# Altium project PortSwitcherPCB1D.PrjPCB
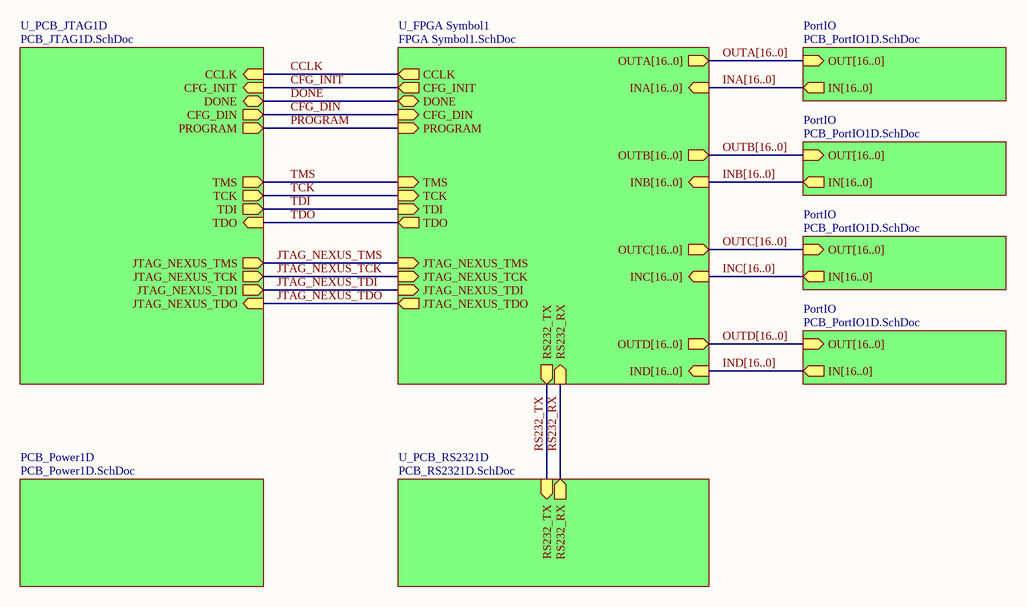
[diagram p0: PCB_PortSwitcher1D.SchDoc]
7 sheets, 152 parts. Net scope: hierarchical (ports join the sheet entries above them; power ports are global).
Board file: PortSwitcher1D.PCBDOC
Sheets:
  PCB_PortSwitcher1D.SchDoc
    PCB_Power1D = PCB_Power1D.SchDoc
    U_PCB_JTAG1D = PCB_JTAG1D.SchDoc
    PortIO = PCB_PortIO1D.SchDoc
    PortIO = PCB_PortIO1D.SchDoc
    PortIO = PCB_PortIO1D.SchDoc
    PortIO = PCB_PortIO1D.SchDoc
    U_FPGA Symbol1 = FPGA Symbol1.SchDoc
      U_FPGA Sheet1 = FPGA Sheet1.SchDoc
    U_PCB_RS2321D = PCB_RS2321D.SchDoc

## Sheet PCB_PortSwitcher1D.SchDoc
size A4; Organization: Altium Limited; Address1: L3, 12a Rodborough Rd; Address2: Frenchs Forest; Address3: NSW; Address4: Australia 2086; DocumentNumber: 1; SheetNumber: 1; SheetTotal: 7

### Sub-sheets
PCB_Power1D = PCB_Power1D.SchDoc: no entries
PortIO = PCB_PortIO1D.SchDoc: OUT[16..0] (in), IN[16..0] (out)
PortIO = PCB_PortIO1D.SchDoc: OUT[16..0] (in), IN[16..0] (out)
PortIO = PCB_PortIO1D.SchDoc: OUT[16..0] (in), IN[16..0] (out)
PortIO = PCB_PortIO1D.SchDoc: OUT[16..0] (in), IN[16..0] (out)
U_FPGA Symbol1 = FPGA Symbol1.SchDoc: CFG_INIT (out), CFG_DIN (in), PROGRAM (in), DONE (bidir), CCLK (out), TMS (in), TCK (in), TDI (in), JTAG_NEXUS_TMS (in), JTAG_NEXUS_TCK (in), JTAG_NEXUS_TDI (in), JTAG_NEXUS_TDO (out), TDO (out), OUTD[16..0] (out), OUTC[16..0] (out), OUTB[16..0] (out), OUTA[16..0] (out), IND[16..0] (in), INC[16..0] (in), INB[16..0] (in), INA[16..0] (in), RS232_TX (out), RS232_RX (in)
U_PCB_JTAG1D = PCB_JTAG1D.SchDoc: TDO (in), TDI (out), TCK (out), TMS (out), DONE (bidir), PROGRAM (out), CCLK (in), JTAG_NEXUS_TMS (out), JTAG_NEXUS_TCK (out), JTAG_NEXUS_TDI (out), JTAG_NEXUS_TDO (in), CFG_DIN (out), CFG_INIT (in)
U_PCB_RS2321D = PCB_RS2321D.SchDoc: RS232_RX (out), RS232_TX (in)

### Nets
CCLK: sheet U_PCB_JTAG1D/CCLK, sheet U_FPGA Symbol1/CCLK
CFG_DIN: sheet U_PCB_JTAG1D/CFG_DIN, sheet U_FPGA Symbol1/CFG_DIN
CFG_INIT: sheet U_PCB_JTAG1D/CFG_INIT, sheet U_FPGA Symbol1/CFG_INIT
DONE: sheet U_PCB_JTAG1D/DONE, sheet U_FPGA Symbol1/DONE
JTAG_NEXUS_TCK: sheet U_PCB_JTAG1D/JTAG_NEXUS_TCK, sheet U_FPGA Symbol1/JTAG_NEXUS_TCK
JTAG_NEXUS_TDI: sheet U_PCB_JTAG1D/JTAG_NEXUS_TDI, sheet U_FPGA Symbol1/JTAG_NEXUS_TDI
JTAG_NEXUS_TDO: sheet U_PCB_JTAG1D/JTAG_NEXUS_TDO, sheet U_FPGA Symbol1/JTAG_NEXUS_TDO
JTAG_NEXUS_TMS: sheet U_PCB_JTAG1D/JTAG_NEXUS_TMS, sheet U_FPGA Symbol1/JTAG_NEXUS_TMS
PROGRAM: sheet U_PCB_JTAG1D/PROGRAM, sheet U_FPGA Symbol1/PROGRAM
RS232_RX: sheet U_FPGA Symbol1/RS232_RX, sheet U_PCB_RS2321D/RS232_RX
RS232_TX: sheet U_FPGA Symbol1/RS232_TX, sheet U_PCB_RS2321D/RS232_TX
TCK: sheet U_PCB_JTAG1D/TCK, sheet U_FPGA Symbol1/TCK
TDI: sheet U_PCB_JTAG1D/TDI, sheet U_FPGA Symbol1/TDI
TDO: sheet U_PCB_JTAG1D/TDO, sheet U_FPGA Symbol1/TDO
TMS: sheet U_PCB_JTAG1D/TMS, sheet U_FPGA Symbol1/TMS

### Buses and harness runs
bus INA[16..0] = sheet PortIO/IN[16..0] = sheet U_FPGA Symbol1/INA[16..0]
bus INB[16..0] = sheet PortIO/IN[16..0] = sheet U_FPGA Symbol1/INB[16..0]
bus INC[16..0] = sheet PortIO/IN[16..0] = sheet U_FPGA Symbol1/INC[16..0]
bus IND[16..0] = sheet PortIO/IN[16..0] = sheet U_FPGA Symbol1/IND[16..0]
bus OUTA[16..0] = sheet PortIO/OUT[16..0] = sheet U_FPGA Symbol1/OUTA[16..0]
bus OUTB[16..0] = sheet PortIO/OUT[16..0] = sheet U_FPGA Symbol1/OUTB[16..0]
bus OUTC[16..0] = sheet PortIO/OUT[16..0] = sheet U_FPGA Symbol1/OUTC[16..0]
bus OUTD[16..0] = sheet PortIO/OUT[16..0] = sheet U_FPGA Symbol1/OUTD[16..0]

## Sheet PCB_Power1D.SchDoc
size A4; Organization: Altium Limited; Address1: L3, 12a Rodborough Rd; Address2: Frenchs Forest; Address3: NSW; Address4: Australia 2086; DocumentNumber: 2; SheetNumber: 2; SheetTotal: 7
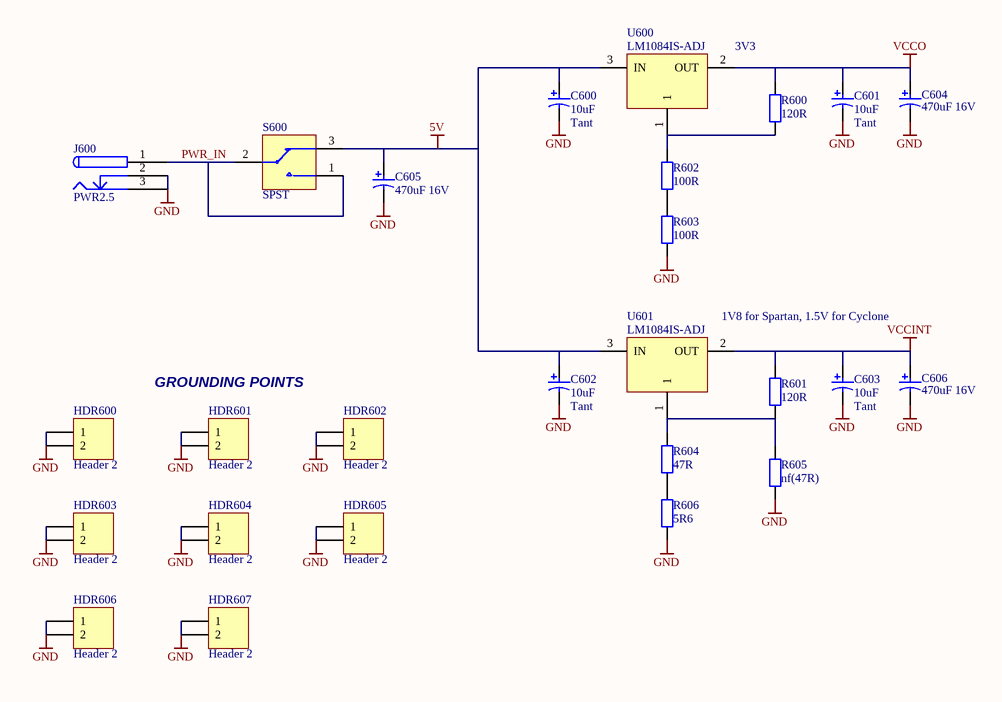
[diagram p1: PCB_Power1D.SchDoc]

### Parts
C600  10uF  Capacitor Type: Tant  [MCCT-B]
C601  10uF  Capacitor Type: Tant  [MCCT-B]
C602  10uF  Capacitor Type: Tant  [MCCT-B]
C603  10uF  Capacitor Type: Tant  [MCCT-B]
C604  470uF 16V  [RB8/3.5]
C605  470uF 16V  [RB8/3.5]
C606  470uF 16V  [RB8/3.5]
HDR600  Header 2  [HDR1X2]
HDR601  Header 2  [HDR1X2]
HDR602  Header 2  [HDR1X2]
HDR603  Header 2  [HDR1X2]
HDR604  Header 2  [HDR1X2]
HDR605  Header 2  [HDR1X2]
HDR606  Header 2  [HDR1X2]
HDR607  Header 2  [HDR1X2]
J600  PWR2.5  [PWR2.5]
R600  120R  [CC2012-0805]
R601  120R  [CC2012-0805]
R602  100R  [CC2012-0805]
R603  100R  [CC2012-0805]
R604  47R  [CC2012-0805]
R605  nf(47R)  [CC2012-0805]
R606  5R6  [CC2012-0805]
S600  SPST  [PCB_SWITCH]
U600  LM1084IS-ADJ  [TO-263]
U601  LM1084IS-ADJ  [TO-263]

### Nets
5V: C600.1 C602.1 C605.1 S600.3 U600.3(IN) U601.3(IN)
GND: C600.2 C601.2 C602.2 C603.2 C604.2 C605.2 C606.2 HDR600.1 HDR600.2 HDR601.1 HDR601.2 HDR602.1 HDR602.2 HDR603.1 HDR603.2 HDR604.1 HDR604.2 HDR605.1 HDR605.2 HDR606.1 HDR606.2 HDR607.1 HDR607.2 J600.2 J600.3 R603.1 R605.1 R606.1
VCCINT: C603.1 C606.1 R601.2 U601.2(OUT)
VCCO: C601.1 C604.1 R600.2 U600.2(OUT)
PWR_IN: J600.1 S600.1 S600.2
NetR600_1: R600.1 R602.2 U600.1
NetR601_1: R601.1 R604.2 R605.2 U601.1
NetR602_1: R602.1 R603.2
NetR604_1: R604.1 R606.2

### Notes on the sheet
- 3V3
- (near U601) 1V8 for Spartan, 1.5V for Cyclone
- (near HDR601) GROUNDING POINTS

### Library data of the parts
C600-C606 = CAP_POLAR: Polar Capacitor; Fitted: True
HDR600-HDR607 = Header 2: Header, 2-Pin; Manufacturer: Generic Components; Class I: Connector; Fitted: True
J600 = PWR2.5: Low Voltage Power Supply Sonnector; Fitted: True
R600-R604 R606 = Res2: Resistor; Manufacturer: Generic Components; Class I: Passive
R605 = Res2: Resistor; Manufacturer: Generic Components; Class I: Passive; Fitted: False
S600 = PCB_MOUNT_SWITCH: SPDT Subminiature Toggle Switch; Fitted: True
U600 U601 = LM1084IS-ADJ: 5A Low Dropout Possitive Regulators; Fitted: True

## Sheet PCB_JTAG1D.SchDoc
size A4; Organization: Altium Limited; Address1: L3, 12a Rodborough Rd; Address2: Frenchs Forest; Address3: NSW; Address4: Australia 2086; DocumentNumber: 4; SheetNumber: 4; SheetTotal: 7
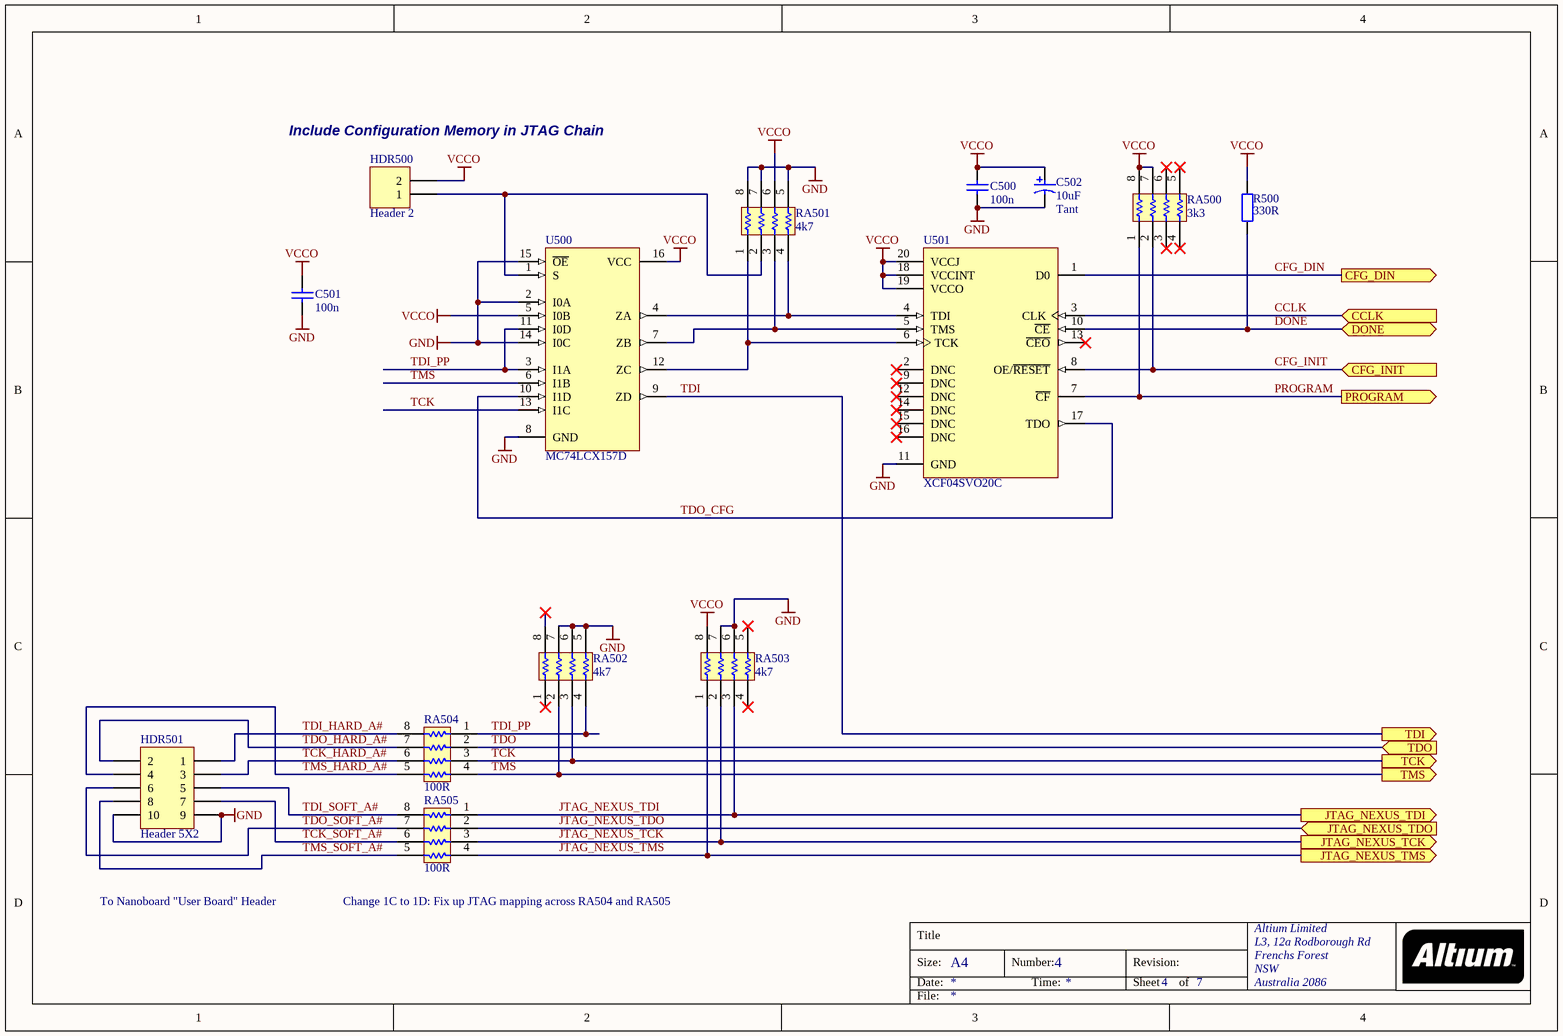
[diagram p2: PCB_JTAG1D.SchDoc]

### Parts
C500  100n  [CC2012-0805]
C501  100n  [CC2012-0805]
C502  10uF  Capacitor Type: Tant  [MCCT-B]
HDR500  Header 2  Usage: Include Configuration Memory in JTAG Chain  [HDR1X2]
HDR501  Header 5X2  Usage: To Nanoboard "User Board" Header  [HDR2X5]
R500  330R  [CC2012-0805]
RA500  3k3  [MNR34]
RA501  4k7  [MNR34]
RA502  4k7  [MNR34]
RA503  4k7  [MNR34]
RA504  100R  [MNR34]
RA505  100R  [MNR34]
U500  MC74LCX157D  [751B-05]
U501  XCF04SVO20C  [VO20]

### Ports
CCLK (in), CFG_DIN (out), CFG_INIT (in), DONE (bidir), JTAG_NEXUS_TCK (out), JTAG_NEXUS_TDI (out), JTAG_NEXUS_TDO (in), JTAG_NEXUS_TMS (out), PROGRAM (out), TCK (out), TDI (out), TDO (in), TMS (out)

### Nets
GND: C500.2 C501.2 C502.2 HDR501.9 HDR501.10 RA501.5 RA501.7 RA501.8 RA502.5 RA502.6 RA502.7 RA503.6 RA503.7 U500.2(I0A) U500.8(GND) U500.14(I0C) U500.15(~{OE}) U501.11(GND)
VCCO: C500.1 C501.1 C502.1 HDR500.2 R500.1 RA500.7 RA500.8 RA501.6 RA503.8 U500.5(I0B) U500.16(VCC) U501.18(VCCINT) U501.19(VCCO) U501.20(VCCJ)
CCLK: U501.3(CLK) ; port CCLK
CFG_DIN: U501.1(D0) ; port CFG_DIN
CFG_INIT: RA500.2 U501.8(OE/~{RESET}) ; port CFG_INIT
DONE: R500.2 U501.10(~{CE}) ; port DONE
JTAG_NEXUS_TCK: RA503.2 RA505.3 ; port JTAG_NEXUS_TCK
JTAG_NEXUS_TDI: RA503.3 RA505.1 ; port JTAG_NEXUS_TDI
JTAG_NEXUS_TDO: RA505.2 ; port JTAG_NEXUS_TDO
JTAG_NEXUS_TMS: RA503.1 RA505.4 ; port JTAG_NEXUS_TMS
PROGRAM: RA500.1 U501.7(~{CF}) ; port PROGRAM
TCK: RA502.3 RA504.3 U500.13(I1C) ; port TCK
TCK_HARD_A#: HDR501.3 RA504.6
TCK_SOFT_A#: HDR501.7 RA505.6
TDI: U500.9(ZD) ; port TDI
TDI_HARD_A#: HDR501.1 RA504.8
TDI_PP: RA502.4 RA504.1 U500.3(I1A) U500.11(I0D)
TDI_SOFT_A#: HDR501.5 RA505.8
TDO: RA504.2 ; port TDO
TDO_CFG: U500.10(I1D) U501.17(TDO)
TDO_HARD_A#: HDR501.2 RA504.7
TDO_SOFT_A#: HDR501.6 RA505.7
TMS: RA502.2 RA504.4 U500.6(I1B) ; port TMS
TMS_HARD_A#: HDR501.4 RA504.5
TMS_SOFT_A#: HDR501.8 RA505.5
NetHDR500_1: HDR500.1 RA501.2 U500.1(S)
NetRA501_1: RA501.1 U500.12(ZC) U501.6(TCK)
NetRA501_3: RA501.3 U500.7(ZB) U501.5(TMS)
NetRA501_4: RA501.4 U500.4(ZA) U501.4(TDI)

Not connected (* = marked no-connect by the designer): RA500 3* 4* 5* 6*; RA502 1* 8*; RA503 4* 5*; U501 2(DNC)* 9(DNC)* 12(DNC)* 13(~{CEO})* 14(DNC)* 15(DNC)* 16(DNC)*

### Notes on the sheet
- (near RA505) Change 1C to 1D: Fix up JTAG mapping across RA504 and RA505

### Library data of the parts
C500 C501 = CAP: Capacitor; Fitted: True
C502 = CAP_POLAR: Polar Capacitor; Fitted: True
HDR500 = Header 2: Header, 2-Pin; Manufacturer: Generic Components; Class I: Connector; Fitted: False
HDR501 = Header 5X2: Header, 5-Pin, Dual row; Manufacturer: Generic Components; Class I: Connector; Fitted: True
R500 = Res2: as R600 on sheet PCB_Power1D
RA500-RA505 = MNR34: 3216x4 Resistor Array; Fitted: True
U500 = MC74LCX157D: Low-Voltage Quad 2-Input Multiplexer with 5V-Tolerant Inputs (Non-Inverting); Manufacturer: ON Semiconductor; Package Information: Latest Revision: Oct-1999; Code - JEDEC: MS-012-AC; Code - IPC: SO16
U501 = XCF04SVO20C: XCF00S Series, Platform Flash In-System Programmable Configuration 3.3V PROM, 20-Pin TSOP, 4-Megabit, Commercial Grade; Manufacturer: Xilinx; Package Information: Latest Revision: ver1.0, May-2003; Code - JEDEC: MO-153-AC

## Sheet PCB_PortIO1D.SchDoc
size A4; Organization: Altium Limited; Address1: L3, 12a Rodborough Rd; Address2: Frenchs Forest; Address3: NSW; Address4: Australia 2086; DocumentNumber: 7; SheetNumber: 7; SheetTotal: 7
Used 4 times, as channels PortIO, PortIO, PortIO, PortIO. Parts and nets are listed once, with the designators drawn on the sheet.
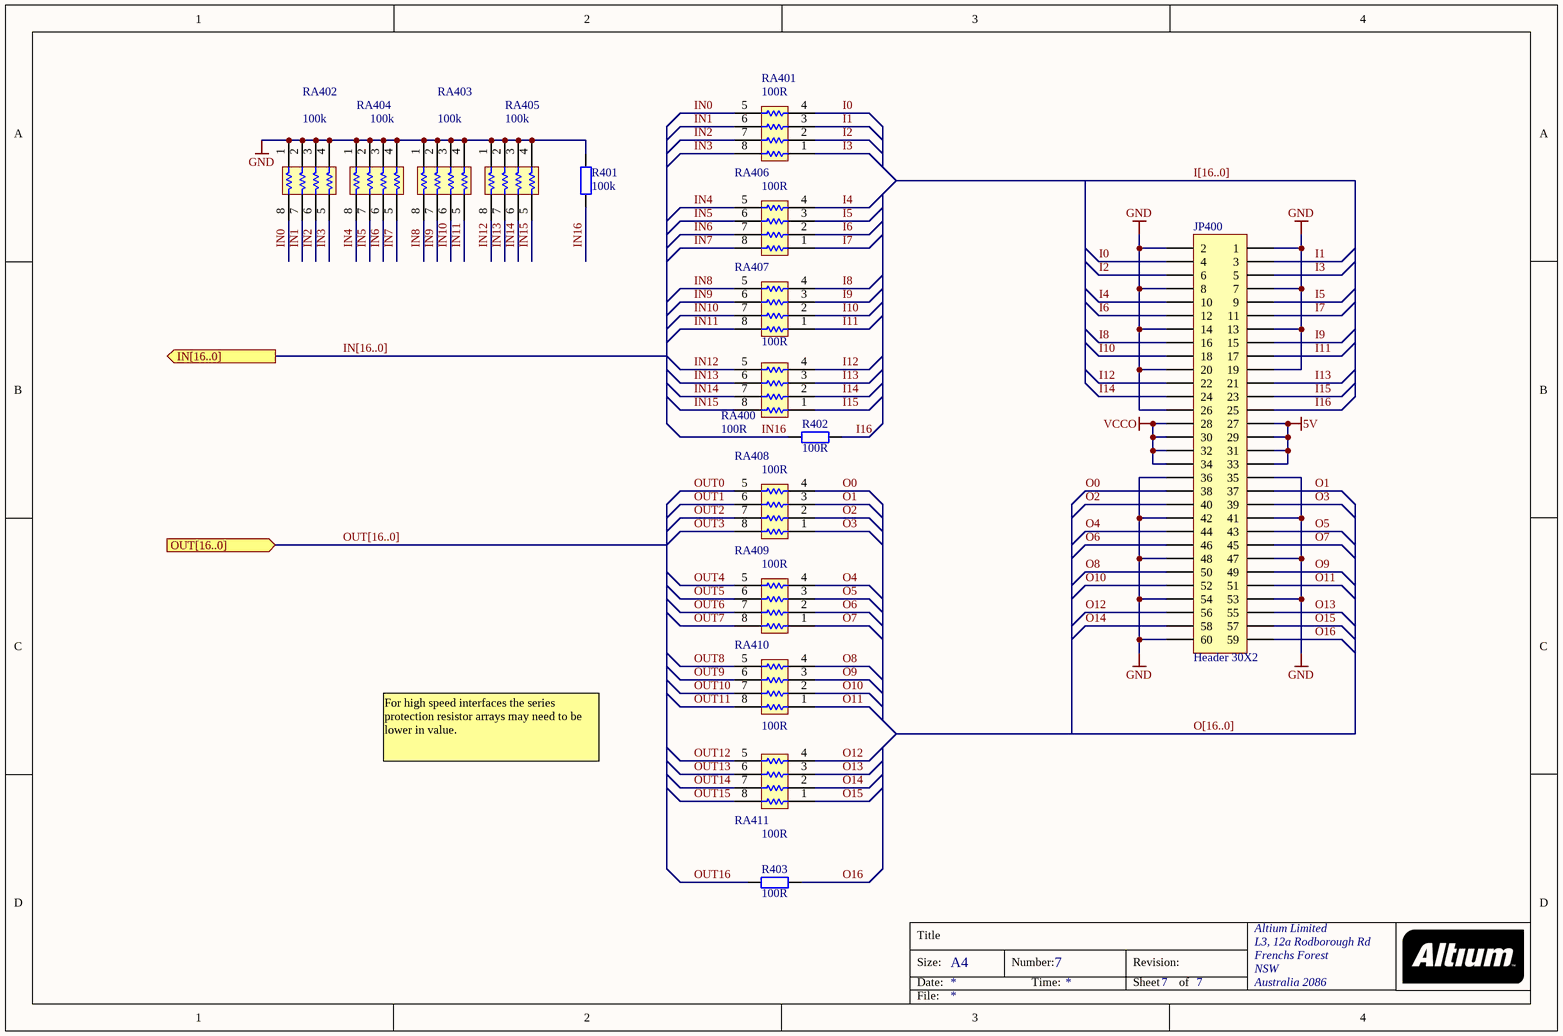
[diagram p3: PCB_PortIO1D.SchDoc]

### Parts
JP400  Header 30X2  [HDR2X30]
R401  100k  [CC2012-0805]
R402  100R  [CC2012-0805]
R403  100R  [CC2012-0805]
RA400  100R  [MNR34]
RA401  100R  [MNR34]
RA402  100k  [MNR34]
RA403  100k  [MNR34]
RA404  100k  [MNR34]
RA405  100k  [MNR34]
RA406  100R  [MNR34]
RA407  100R  [MNR34]
RA408  100R  [MNR34]
RA409  100R  [MNR34]
RA410  100R  [MNR34]
RA411  100R  [MNR34]

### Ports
IN[16..0] (out), OUT[16..0] (in)

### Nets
5V: JP400.27 JP400.29 JP400.31 JP400.33
GND: JP400.1 JP400.2 JP400.7 JP400.8 JP400.13 JP400.14 JP400.19 JP400.20 JP400.26 JP400.35 JP400.36 JP400.41 JP400.42 JP400.47 JP400.48 JP400.53 JP400.54 JP400.60 R401.1 RA402.1 RA402.2 RA402.3 RA402.4 RA403.1 RA403.2 RA403.3 RA403.4 RA404.1 RA404.2 RA404.3 RA404.4 RA405.1 RA405.2 RA405.3 RA405.4
VCCO: JP400.28 JP400.30 JP400.32 JP400.34
I0: JP400.4 RA401.4
I1: JP400.3 RA401.3
I2: JP400.6 RA401.2
I3: JP400.5 RA401.1
I4: JP400.10 RA406.4
I5: JP400.9 RA406.3
I6: JP400.12 RA406.2
I7: JP400.11 RA406.1
I8: JP400.16 RA407.4
I9: JP400.15 RA407.3
I10: JP400.18 RA407.2
I11: JP400.17 RA407.1
I12: JP400.22 RA400.4
I13: JP400.21 RA400.3
I14: JP400.24 RA400.2
I15: JP400.23 RA400.1
I16: JP400.25 R402.2
IN0: RA401.5 RA402.8
IN1: RA401.6 RA402.7
IN2: RA401.7 RA402.6
IN3: RA401.8 RA402.5
IN4: RA404.8 RA406.5
IN5: RA404.7 RA406.6
IN6: RA404.6 RA406.7
IN7: RA404.5 RA406.8
IN8: RA403.8 RA407.5
IN9: RA403.7 RA407.6
IN10: RA403.6 RA407.7
IN11: RA403.5 RA407.8
IN12: RA400.5 RA405.8
IN13: RA400.6 RA405.7
IN14: RA400.7 RA405.6
IN15: RA400.8 RA405.5
IN16: R401.2 R402.1
O0: JP400.38 RA408.4
O1: JP400.37 RA408.3
O2: JP400.40 RA408.2
O3: JP400.39 RA408.1
O4: JP400.44 RA409.4
O5: JP400.43 RA409.3
O6: JP400.46 RA409.2
O7: JP400.45 RA409.1
O8: JP400.50 RA410.4
O9: JP400.49 RA410.3
O10: JP400.52 RA410.2
O11: JP400.51 RA410.1
O12: JP400.56 RA411.4
O13: JP400.55 RA411.3
O14: JP400.58 RA411.2
O15: JP400.57 RA411.1
O16: JP400.59 R403.2
OUT0: RA408.5
OUT1: RA408.6
OUT2: RA408.7
OUT3: RA408.8
OUT4: RA409.5
OUT5: RA409.6
OUT6: RA409.7
OUT7: RA409.8
OUT8: RA410.5
OUT9: RA410.6
OUT10: RA410.7
OUT11: RA410.8
OUT12: RA411.5
OUT13: RA411.6
OUT14: RA411.7
OUT15: RA411.8
OUT16: R403.1

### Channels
PortIO: designators end in _PortIOD
PortIO: designators end in _PortIOC
PortIO: designators end in _PortIOB
PortIO: designators end in _PortIOA

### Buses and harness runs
bus I[16..0]
bus IN[16..0] = port IN[16..0]
bus O[16..0]
bus OUT[16..0] = port OUT[16..0]

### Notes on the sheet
- For high speed interfaces the series protection resistor arrays may need to be lower in value.

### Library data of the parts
JP400 = Header 30X2: Header, 30-Pin, Dual row; Manufacturer: Generic Components; Class I: Connector
R401-R403 = Res2: as R600 on sheet PCB_Power1D
RA400-RA411 = MNR34: 3216x4 Resistor Array; Fitted: True

## Sheet FPGA Symbol1.SchDoc
size A4; Organization: Altium Limited; Address1: L3, 12a Rodborough Rd; Address2: Frenchs Forest; Address3: NSW; Address4: Australia 2086; DocumentNumber: 6; SheetNumber: 6; SheetTotal: 7
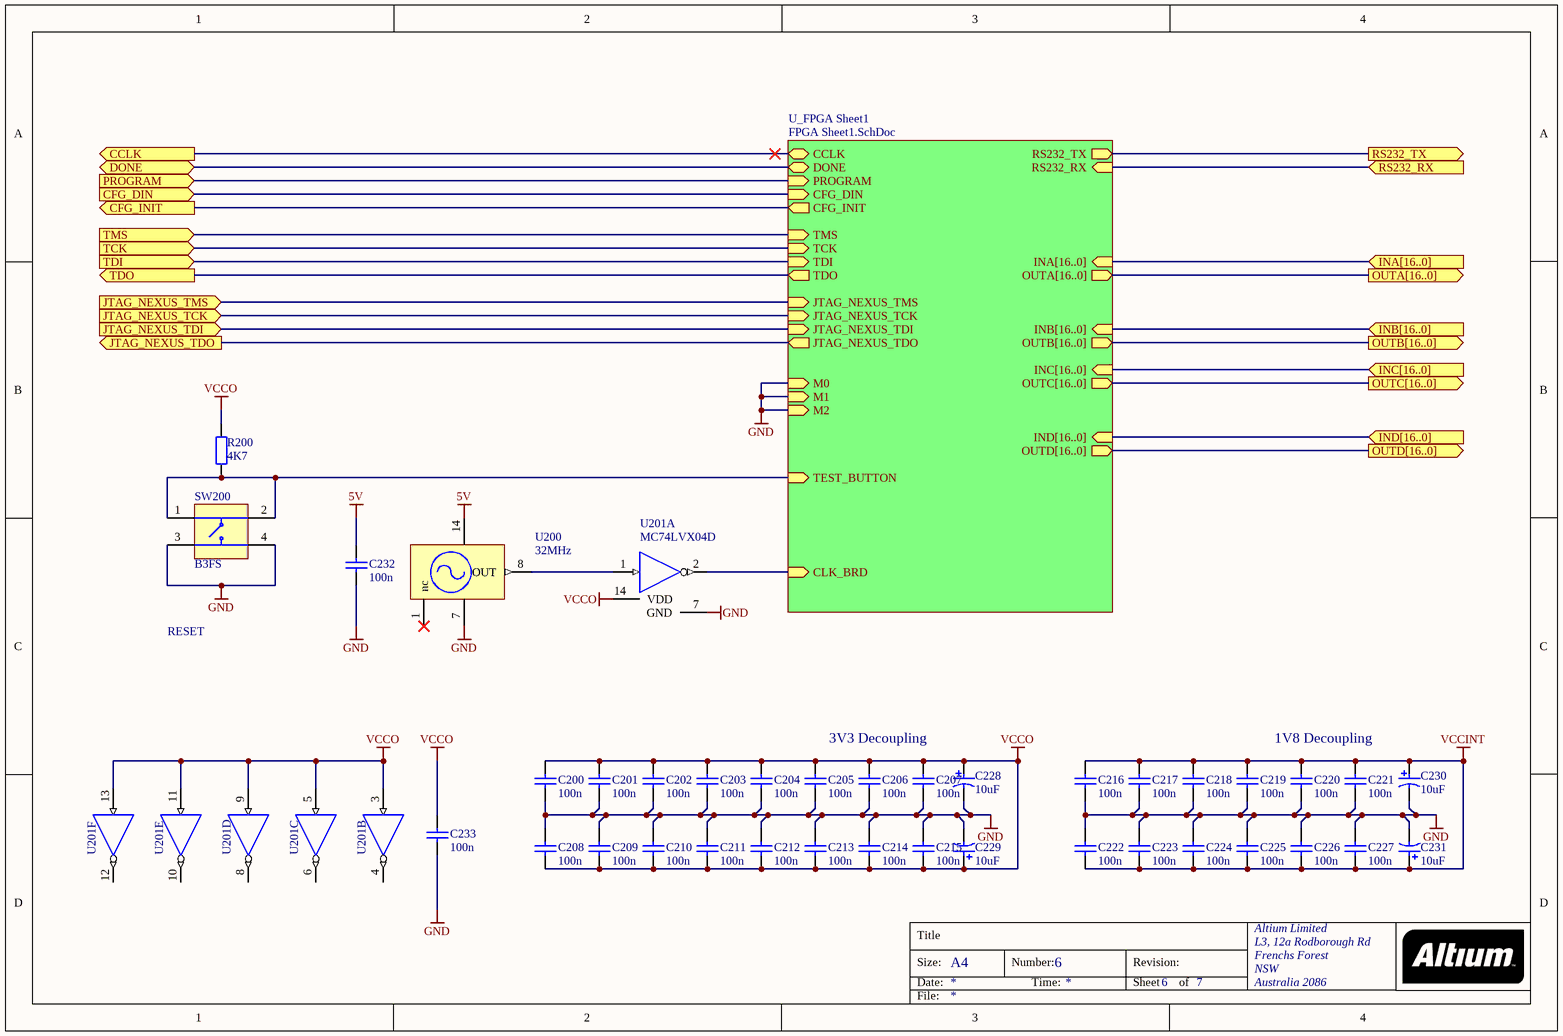
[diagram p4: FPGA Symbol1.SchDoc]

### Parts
C200  100n  [CC2012-0805]
C201  100n  [CC2012-0805]
C202  100n  [CC2012-0805]
C203  100n  [CC2012-0805]
C204  100n  [CC2012-0805]
C205  100n  [CC2012-0805]
C206  100n  [CC2012-0805]
C207  100n  [CC2012-0805]
C208  100n  [CC2012-0805]
C209  100n  [CC2012-0805]
C210  100n  [CC2012-0805]
C211  100n  [CC2012-0805]
C212  100n  [CC2012-0805]
C213  100n  [CC2012-0805]
C214  100n  [CC2012-0805]
C215  100n  [CC2012-0805]
C216  100n  [CC2012-0805]
C217  100n  [CC2012-0805]
C218  100n  [CC2012-0805]
C219  100n  [CC2012-0805]
C220  100n  [CC2012-0805]
C221  100n  [CC2012-0805]
C222  100n  [CC2012-0805]
C223  100n  [CC2012-0805]
C224  100n  [CC2012-0805]
C225  100n  [CC2012-0805]
C226  100n  [CC2012-0805]
C227  100n  [CC2012-0805]
C228  10uF  [MCCT-B]
C229  10uF  [MCCT-B]
C230  10uF  [MCCT-B]
C231  10uF  [MCCT-B]
C232  100n  [CC2012-0805]
C233  100n  [CC2012-0805]
R200  4K7  [CC2012-0805]
SW200  B3FS  [B3FS_SWITCH]
U200  32MHz  [XO600CP]
U201  MC74LVX04D  [751A-03]  (parts A,B,C,D,E,F of 6)

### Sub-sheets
U_FPGA Sheet1 = FPGA Sheet1.SchDoc: CFG_DIN (in), CFG_INIT (out), CLK_BRD (in), INA[16..0] (in), INC[16..0] (in), JTAG_NEXUS_TCK (in), JTAG_NEXUS_TDI (in), JTAG_NEXUS_TDO (out), JTAG_NEXUS_TMS (in), OUTA[16..0] (out), OUTB[16..0] (out), OUTC[16..0] (out), OUTD[16..0] (out), RS232_RX (in), RS232_TX (out), TEST_BUTTON (in), CCLK (bidir), DONE (bidir), M0 (in), M1 (in), M2 (in), PROGRAM (in), TCK (in), TDI (in), TDO (out), TMS (in), INB[16..0] (in), IND[16..0] (in)

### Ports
CCLK (out), CFG_DIN (in), CFG_INIT (out), DONE (bidir), INA[16..0] (in), INB[16..0] (in), INC[16..0] (in), IND[16..0] (in), JTAG_NEXUS_TCK (in), JTAG_NEXUS_TDI (in), JTAG_NEXUS_TDO (out), JTAG_NEXUS_TMS (in), OUTA[16..0] (out), OUTB[16..0] (out), OUTC[16..0] (out), OUTD[16..0] (out), PROGRAM (in), RS232_RX (in), RS232_TX (out), TCK (in), TDI (in), TDO (out), TMS (in)

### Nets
5V: C232.1 U200.14(VCC)
GND: C200.2 C201.2 C202.2 C203.2 C204.2 C205.2 C206.2 C207.2 C208.1 C209.1 C210.1 C211.1 C212.1 C213.1 C214.1 C215.1 C216.2 C217.2 C218.2 C219.2 C220.2 C221.2 C222.1 C223.1 C224.1 C225.1 C226.1 C227.1 C228.2 C229.2 C230.2 C231.2 C232.2 C233.2 SW200.3 SW200.4 U200.7(GND) U201.7(GND) ; sheet U_FPGA Sheet1/M0, sheet U_FPGA Sheet1/M1, sheet U_FPGA Sheet1/M2
VCCINT: C216.1 C217.1 C218.1 C219.1 C220.1 C221.1 C222.2 C223.2 C224.2 C225.2 C226.2 C227.2 C230.1 C231.1
VCCO: C200.1 C201.1 C202.1 C203.1 C204.1 C205.1 C206.1 C207.1 C208.2 C209.2 C210.2 C211.2 C212.2 C213.2 C214.2 C215.2 C228.1 C229.1 C233.1 R200.2 U201.3(IN) U201.5(IN) U201.9(IN) U201.11(IN) U201.13(IN) U201.14(VDD)
CCLK: port CCLK, sheet U_FPGA Sheet1/CCLK
CFG_DIN: port CFG_DIN, sheet U_FPGA Sheet1/CFG_DIN
CFG_INIT: port CFG_INIT, sheet U_FPGA Sheet1/CFG_INIT
CLK_BRD: U201.2(~{OUT}) ; sheet U_FPGA Sheet1/CLK_BRD
DONE: port DONE, sheet U_FPGA Sheet1/DONE
JTAG_NEXUS_TCK: port JTAG_NEXUS_TCK, sheet U_FPGA Sheet1/JTAG_NEXUS_TCK
JTAG_NEXUS_TDI: port JTAG_NEXUS_TDI, sheet U_FPGA Sheet1/JTAG_NEXUS_TDI
JTAG_NEXUS_TDO: port JTAG_NEXUS_TDO, sheet U_FPGA Sheet1/JTAG_NEXUS_TDO
JTAG_NEXUS_TMS: port JTAG_NEXUS_TMS, sheet U_FPGA Sheet1/JTAG_NEXUS_TMS
PROGRAM: port PROGRAM, sheet U_FPGA Sheet1/PROGRAM
RS232_RX: port RS232_RX, sheet U_FPGA Sheet1/RS232_RX
RS232_TX: port RS232_TX, sheet U_FPGA Sheet1/RS232_TX
TCK: port TCK, sheet U_FPGA Sheet1/TCK
TDI: port TDI, sheet U_FPGA Sheet1/TDI
TDO: port TDO, sheet U_FPGA Sheet1/TDO
TEST_BUTTON: R200.1 SW200.1 SW200.2 ; sheet U_FPGA Sheet1/TEST_BUTTON
TMS: port TMS, sheet U_FPGA Sheet1/TMS
NetU200_8: U200.8(OUT) U201.1(IN)

Not connected (* = marked no-connect by the designer): U200 1(nc)*; U201 4(~{OUT}) 6(~{OUT}) 8(~{OUT}) 10(~{OUT}) 12(~{OUT})

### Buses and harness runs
bus port INA[16..0] = sheet U_FPGA Sheet1/INA[16..0]
bus port INB[16..0] = sheet U_FPGA Sheet1/INB[16..0]
bus port INC[16..0] = sheet U_FPGA Sheet1/INC[16..0]
bus port IND[16..0] = sheet U_FPGA Sheet1/IND[16..0]
bus port OUTA[16..0] = sheet U_FPGA Sheet1/OUTA[16..0]
bus port OUTB[16..0] = sheet U_FPGA Sheet1/OUTB[16..0]
bus port OUTC[16..0] = sheet U_FPGA Sheet1/OUTC[16..0]
bus port OUTD[16..0] = sheet U_FPGA Sheet1/OUTD[16..0]

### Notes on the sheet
- RESET
- 3V3 Decoupling
- 1V8 Decoupling

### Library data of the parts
C200-C227 C232 C233 = CAP: Capacitor; Fitted: True
C228-C231 = CAP_POLAR: Polar Capacitor
R200 = Res2: as R600 on sheet PCB_Power1D
SW200 = B3FS: SPNA SMD Keyboard Switch; Fitted: True
U200 = XO_CAN_DIP14_1M: IC, Oscillator, Canned, CMOS o/p, General Purpose, No Enable/Disable, 32MHz; Text Field1: TBA
U201 = MC74LVX04D: Hex Inverter with 5V-Tolerant Inputs; Manufacturer: ON Semiconductor; Code - JEDEC: MS-012-AB; Code - IPC: SO14

## Sheet FPGA Sheet1.SchDoc
size A2; Generated From FPGA Project: PortSwitcherFPGA1C.PrjFpg; UNUSED_SPECIAL: RouteSeparate; UNUSED_IO: NoERC; VREF: NoERC; UNUSED_INPUT: NoERC; DocumentNumber: 5; SheetNumber: 5; SheetTotal: 7
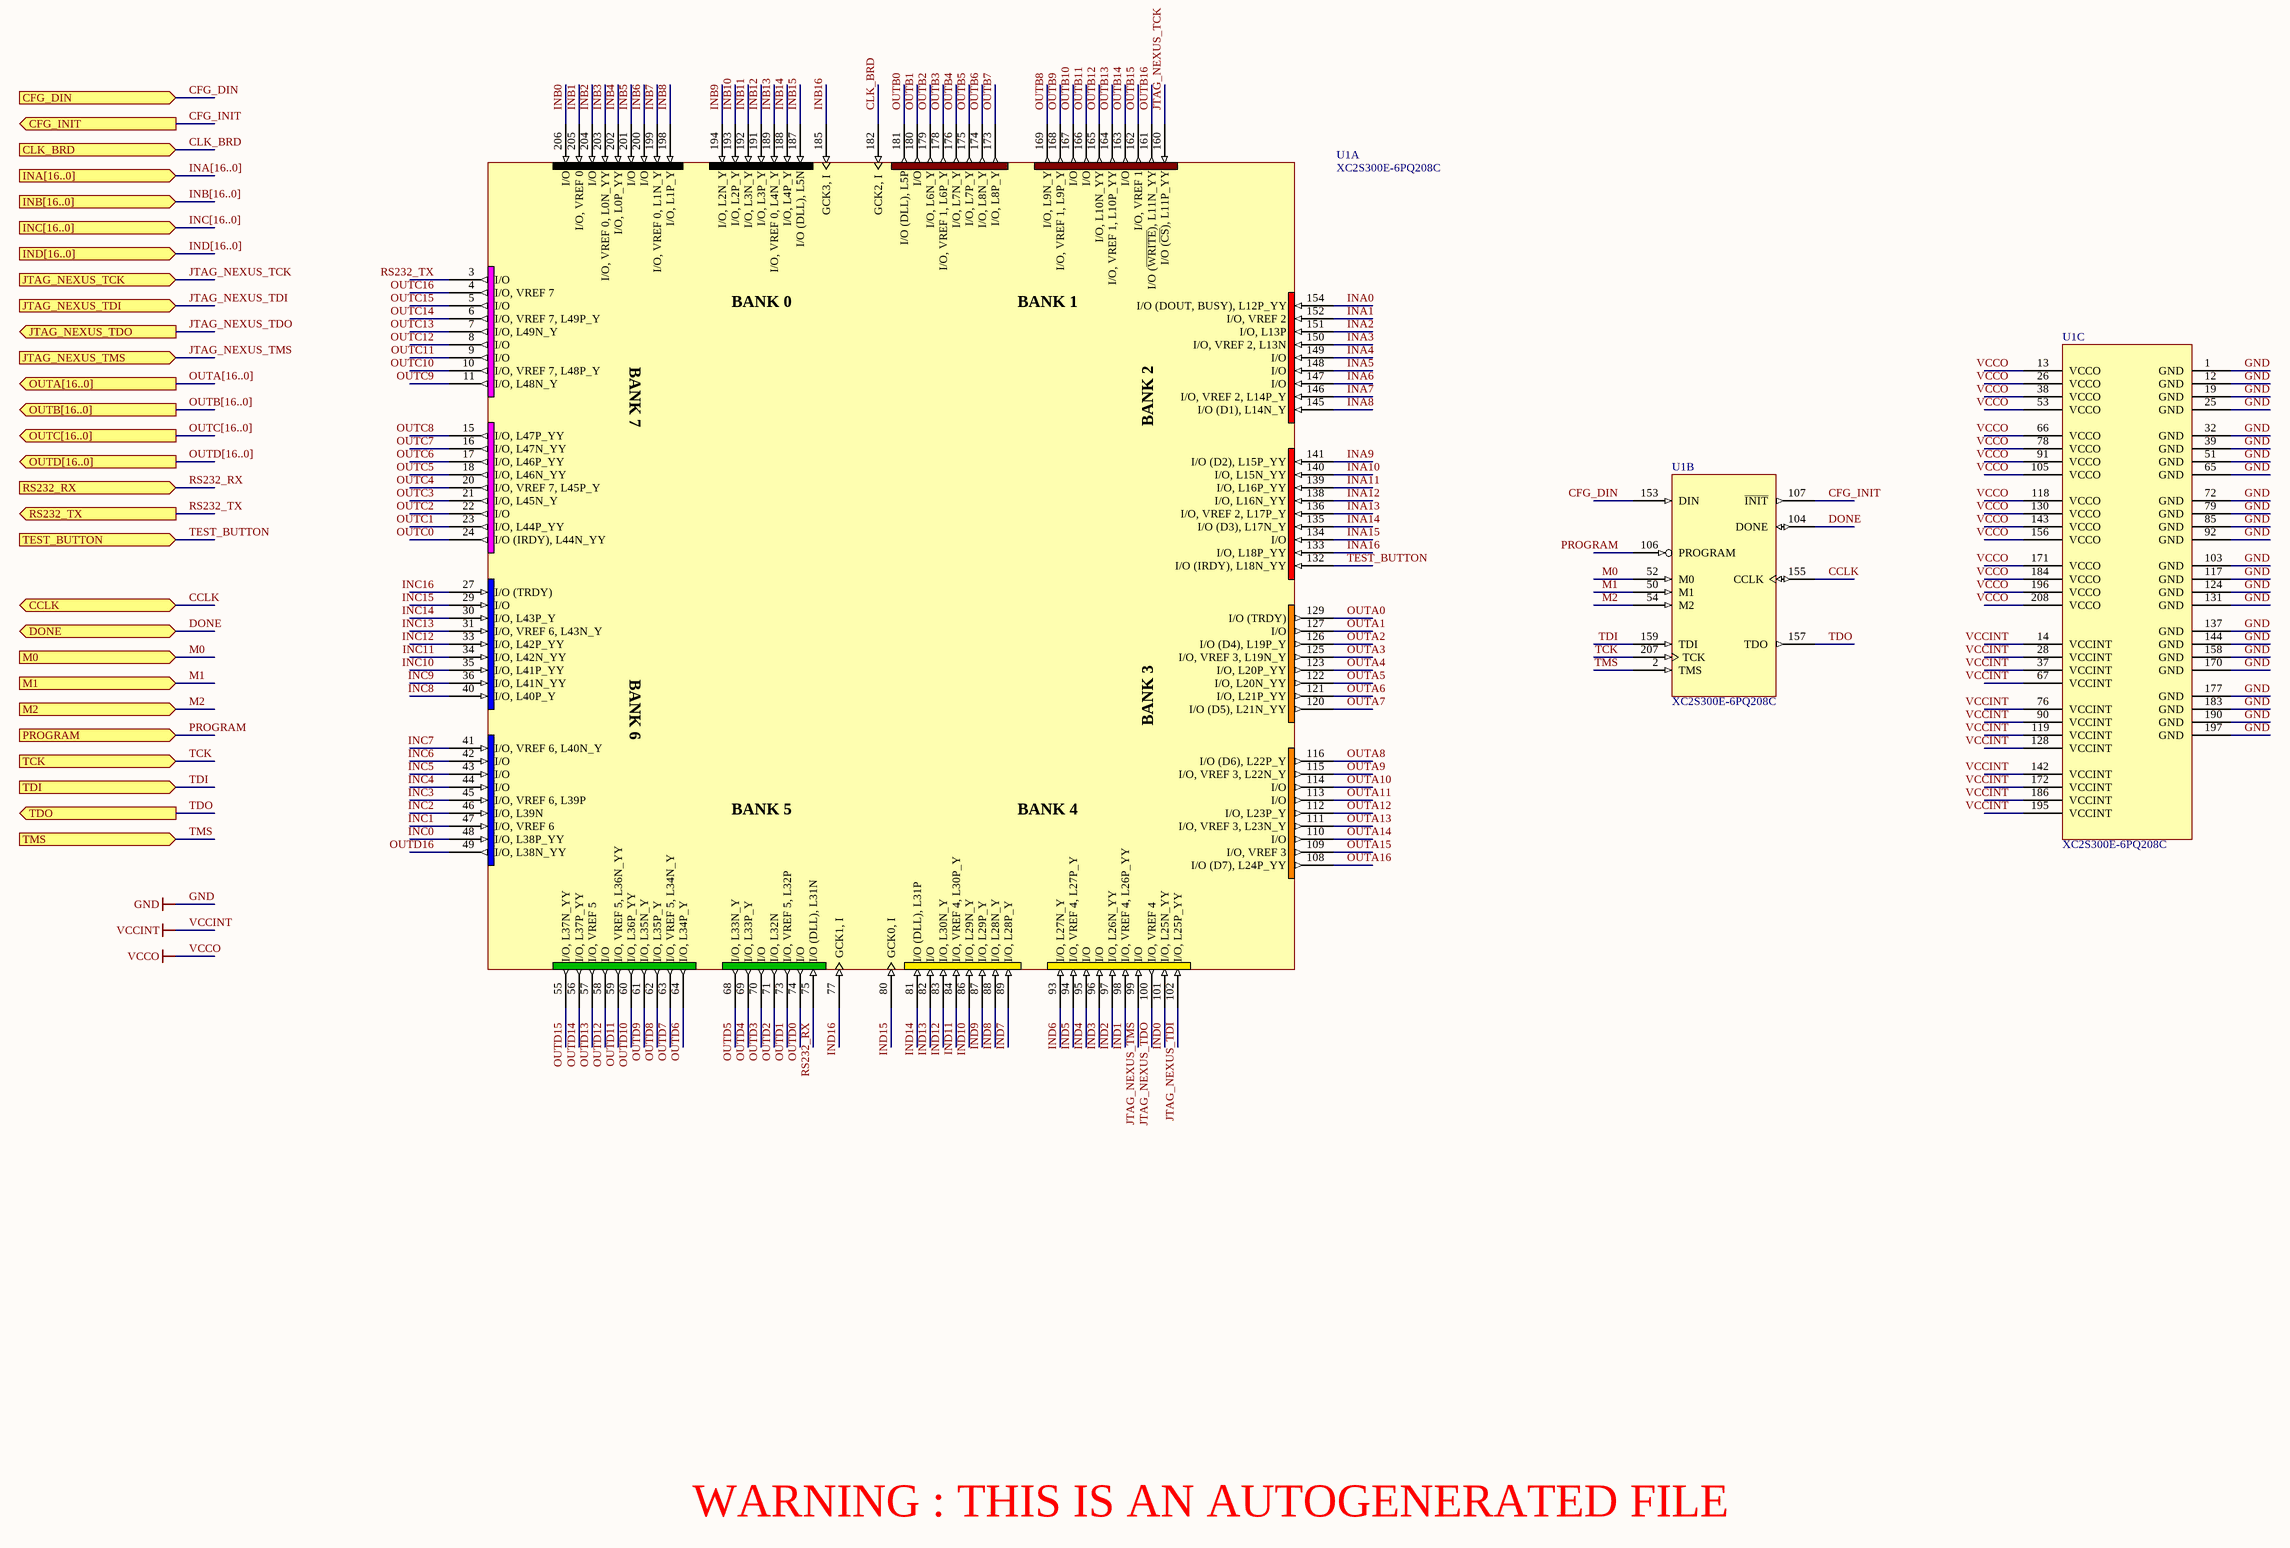
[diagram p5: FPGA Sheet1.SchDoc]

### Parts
U1  XC2S300E-6PQ208C  [PQ208]  (parts A,B,C of 3)

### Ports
CCLK (bidir), CFG_DIN (in), CFG_INIT (out), CLK_BRD (in), DONE (bidir), INA[16..0] (in), INB[16..0] (in), INC[16..0] (in), IND[16..0] (in), JTAG_NEXUS_TCK (in), JTAG_NEXUS_TDI (in), JTAG_NEXUS_TDO (out), JTAG_NEXUS_TMS (in), M0 (in), M1 (in), M2 (in), OUTA[16..0] (out), OUTB[16..0] (out), OUTC[16..0] (out), OUTD[16..0] (out), PROGRAM (in), RS232_RX (in), RS232_TX (out), TCK (in), TDI (in), TDO (out), TEST_BUTTON (in), TMS (in)

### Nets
GND: U1.1(GND) U1.12(GND) U1.19(GND) U1.25(GND) U1.32(GND) U1.39(GND) U1.50(M1) U1.51(GND) U1.52(M0) U1.54(M2) U1.65(GND) U1.72(GND) U1.79(GND) U1.85(GND) U1.92(GND) U1.103(GND) U1.117(GND) U1.124(GND) U1.131(GND) U1.137(GND) U1.144(GND) U1.158(GND) U1.170(GND) U1.177(GND) U1.183(GND) U1.190(GND) U1.197(GND) ; port M0, port M1, port M2  [also labelled M0, M1, M2]
VCCINT: U1.14(VCCINT) U1.28(VCCINT) U1.37(VCCINT) U1.67(VCCINT) U1.76(VCCINT) U1.90(VCCINT) U1.119(VCCINT) U1.128(VCCINT) U1.142(VCCINT) U1.172(VCCINT) U1.186(VCCINT) U1.195(VCCINT)
VCCO: U1.13(VCCO) U1.26(VCCO) U1.38(VCCO) U1.53(VCCO) U1.66(VCCO) U1.78(VCCO) U1.91(VCCO) U1.105(VCCO) U1.118(VCCO) U1.130(VCCO) U1.143(VCCO) U1.156(VCCO) U1.171(VCCO) U1.184(VCCO) U1.196(VCCO) U1.208(VCCO)
CCLK: U1.155(CCLK) ; port CCLK
CFG_DIN: U1.153(DIN) ; port CFG_DIN
CFG_INIT: U1.107(~{INIT}) ; port CFG_INIT
CLK_BRD: U1.182(GCK2,_I) ; port CLK_BRD
DONE: U1.104(DONE) ; port DONE
INA0: U1.154(I/O_(DOUT,_BUSY),_L12P_YY)
INA1: U1.152(I/O,_VREF_2)
INA2: U1.151(I/O,_L13P)
INA3: U1.150(I/O,_VREF_2,_L13N)
INA4: U1.149(I/O)
INA5: U1.148(I/O)
INA6: U1.147(I/O)
INA7: U1.146(I/O,_VREF_2,_L14P_Y)
INA8: U1.145(I/O_(D1),_L14N_Y)
INA9: U1.141(I/O_(D2),_L15P_YY)
INA10: U1.140(I/O,_L15N_YY)
INA11: U1.139(I/O,_L16P_YY)
INA12: U1.138(I/O,_L16N_YY)
INA13: U1.136(I/O,_VREF_2,_L17P_Y)
INA14: U1.135(I/O_(D3),_L17N_Y)
INA15: U1.134(I/O)
INA16: U1.133(I/O,_L18P_YY)
INB0: U1.206(I/O)
INB1: U1.205(I/O,_VREF_0)
INB2: U1.204(I/O)
INB3: U1.203(I/O,_VREF_0,_L0N_YY)
INB4: U1.202(I/O,_L0P_YY)
INB5: U1.201(I/O)
INB6: U1.200(I/O)
INB7: U1.199(I/O,_VREF_0,_L1N_Y)
INB8: U1.198(I/O,_L1P_Y)
INB9: U1.194(I/O,_L2N_Y)
INB10: U1.193(I/O,_L2P_Y)
INB11: U1.192(I/O,_L3N_Y)
INB12: U1.191(I/O,_L3P_Y)
INB13: U1.189(I/O,_VREF_0,_L4N_Y)
INB14: U1.188(I/O,_L4P_Y)
INB15: U1.187(I/O_(DLL),_L5N)
INB16: U1.185(GCK3,_I)
INC0: U1.48(I/O,_L38P_YY)
INC1: U1.47(I/O,_VREF_6)
INC2: U1.46(I/O,_L39N)
INC3: U1.45(I/O,_VREF_6,_L39P)
INC4: U1.44(I/O)
INC5: U1.43(I/O)
INC6: U1.42(I/O)
INC7: U1.41(I/O,_VREF_6,_L40N_Y)
INC8: U1.40(I/O,_L40P_Y)
INC9: U1.36(I/O,_L41N_YY)
INC10: U1.35(I/O,_L41P_YY)
INC11: U1.34(I/O,_L42N_YY)
INC12: U1.33(I/O,_L42P_YY)
INC13: U1.31(I/O,_VREF_6,_L43N_Y)
INC14: U1.30(I/O,_L43P_Y)
INC15: U1.29(I/O)
INC16: U1.27(I/O_(TRDY))
IND0: U1.101(I/O,_L25N_YY)
IND1: U1.98(I/O,_VREF_4,_L26P_YY)
IND2: U1.97(I/O,_L26N_YY)
IND3: U1.96(I/O)
IND4: U1.95(I/O)
IND5: U1.94(I/O,_VREF_4,_L27P_Y)
IND6: U1.93(I/O,_L27N_Y)
IND7: U1.89(I/O,_L28P_Y)
IND8: U1.88(I/O,_L28N_Y)
IND9: U1.87(I/O,_L29P_Y)
IND10: U1.86(I/O,_L29N_Y)
IND11: U1.84(I/O,_VREF_4,_L30P_Y)
IND12: U1.83(I/O,_L30N_Y)
IND13: U1.82(I/O)
IND14: U1.81(I/O_(DLL),_L31P)
IND15: U1.80(GCK0,_I)
IND16: U1.77(GCK1,_I)
JTAG_NEXUS_TCK: U1.160(I/O_(~{CS}),_L11P_YY) ; port JTAG_NEXUS_TCK
JTAG_NEXUS_TDI: U1.102(I/O,_L25P_YY) ; port JTAG_NEXUS_TDI
JTAG_NEXUS_TDO: U1.100(I/O,_VREF_4) ; port JTAG_NEXUS_TDO
JTAG_NEXUS_TMS: U1.99(I/O) ; port JTAG_NEXUS_TMS
OUTA0: U1.129(I/O_(TRDY))
OUTA1: U1.127(I/O)
OUTA2: U1.126(I/O_(D4),_L19P_Y)
OUTA3: U1.125(I/O,_VREF_3,_L19N_Y)
OUTA4: U1.123(I/O,_L20P_YY)
OUTA5: U1.122(I/O,_L20N_YY)
OUTA6: U1.121(I/O,_L21P_YY)
OUTA7: U1.120(I/O_(D5),_L21N_YY)
OUTA8: U1.116(I/O_(D6),_L22P_Y)
OUTA9: U1.115(I/O,_VREF_3,_L22N_Y)
OUTA10: U1.114(I/O)
OUTA11: U1.113(I/O)
OUTA12: U1.112(I/O,_L23P_Y)
OUTA13: U1.111(I/O,_VREF_3,_L23N_Y)
OUTA14: U1.110(I/O)
OUTA15: U1.109(I/O,_VREF_3)
OUTA16: U1.108(I/O_(D7),_L24P_YY)
OUTB0: U1.181(I/O_(DLL),_L5P)
OUTB1: U1.180(I/O)
OUTB2: U1.179(I/O,_L6N_Y)
OUTB3: U1.178(I/O,_VREF_1,_L6P_Y)
OUTB4: U1.176(I/O,_L7N_Y)
OUTB5: U1.175(I/O,_L7P_Y)
OUTB6: U1.174(I/O,_L8N_Y)
OUTB7: U1.173(I/O,_L8P_Y)
OUTB8: U1.169(I/O,_L9N_Y)
OUTB9: U1.168(I/O,_VREF_1,_L9P_Y)
OUTB10: U1.167(I/O)
OUTB11: U1.166(I/O)
OUTB12: U1.165(I/O,_L10N_YY)
OUTB13: U1.164(I/O,_VREF_1,_L10P_YY)
OUTB14: U1.163(I/O)
OUTB15: U1.162(I/O,_VREF_1)
OUTB16: U1.161(I/O_(~{WRITE}),_L11N_YY)
OUTC0: U1.24(I/O_(IRDY),_L44N_YY)
OUTC1: U1.23(I/O,_L44P_YY)
OUTC2: U1.22(I/O)
OUTC3: U1.21(I/O,_L45N_Y)
OUTC4: U1.20(I/O,_VREF_7,_L45P_Y)
OUTC5: U1.18(I/O,_L46N_YY)
OUTC6: U1.17(I/O,_L46P_YY)
OUTC7: U1.16(I/O,_L47N_YY)
OUTC8: U1.15(I/O,_L47P_YY)
OUTC9: U1.11(I/O,_L48N_Y)
OUTC10: U1.10(I/O,_VREF_7,_L48P_Y)
OUTC11: U1.9(I/O)
OUTC12: U1.8(I/O)
OUTC13: U1.7(I/O,_L49N_Y)
OUTC14: U1.6(I/O,_VREF_7,_L49P_Y)
OUTC15: U1.5(I/O)
OUTC16: U1.4(I/O,_VREF_7)
OUTD0: U1.74(I/O)
OUTD1: U1.73(I/O,_VREF_5,_L32P)
OUTD2: U1.71(I/O,_L32N)
OUTD3: U1.70(I/O)
OUTD4: U1.69(I/O,_L33P_Y)
OUTD5: U1.68(I/O,_L33N_Y)
OUTD6: U1.64(I/O,_L34P_Y)
OUTD7: U1.63(I/O,_VREF_5,_L34N_Y)
OUTD8: U1.62(I/O,_L35P_Y)
OUTD9: U1.61(I/O,_L35N_Y)
OUTD10: U1.60(I/O,_L36P_YY)
OUTD11: U1.59(I/O,_VREF_5,_L36N_YY)
OUTD12: U1.58(I/O)
OUTD13: U1.57(I/O,_VREF_5)
OUTD14: U1.56(I/O,_L37P_YY)
OUTD15: U1.55(I/O,_L37N_YY)
OUTD16: U1.49(I/O,_L38N_YY)
PROGRAM: U1.106(PROGRAM) ; port PROGRAM
RS232_RX: U1.75(I/O_(DLL),_L31N) ; port RS232_RX
RS232_TX: U1.3(I/O) ; port RS232_TX
TCK: U1.207(TCK) ; port TCK
TDI: U1.159(TDI) ; port TDI
TDO: U1.157(TDO) ; port TDO
TEST_BUTTON: U1.132(I/O_(IRDY),_L18N_YY) ; port TEST_BUTTON
TMS: U1.2(TMS) ; port TMS

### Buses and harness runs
bus INA[16..0] = port INA[16..0]
bus INB[16..0] = port INB[16..0]
bus INC[16..0] = port INC[16..0]
bus IND[16..0] = port IND[16..0]
bus OUTA[16..0] = port OUTA[16..0]
bus OUTB[16..0] = port OUTB[16..0]
bus OUTC[16..0] = port OUTC[16..0]
bus OUTD[16..0] = port OUTD[16..0]

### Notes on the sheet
- WARNING : THIS IS AN AUTOGENERATED FILE

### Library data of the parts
U1 = XC2S300E-6PQ208C: Spartan-IIE 1.8V FPGA, 208-Pin PQFP, Standard Performance, Commercial Grade; Package Information: Latest Revision: ver1.1, Oct-2002; Code - JEDEC: MS-029-FA-1

## Sheet PCB_RS2321D.SchDoc
size A4; Organization: Altium Limited; Address1: L3, 12a Rodborough Rd; Address2: Frenchs Forest; Address3: NSW; Address4: Australia 2086; DocumentNumber: 3; SheetNumber: 3; SheetTotal: 7
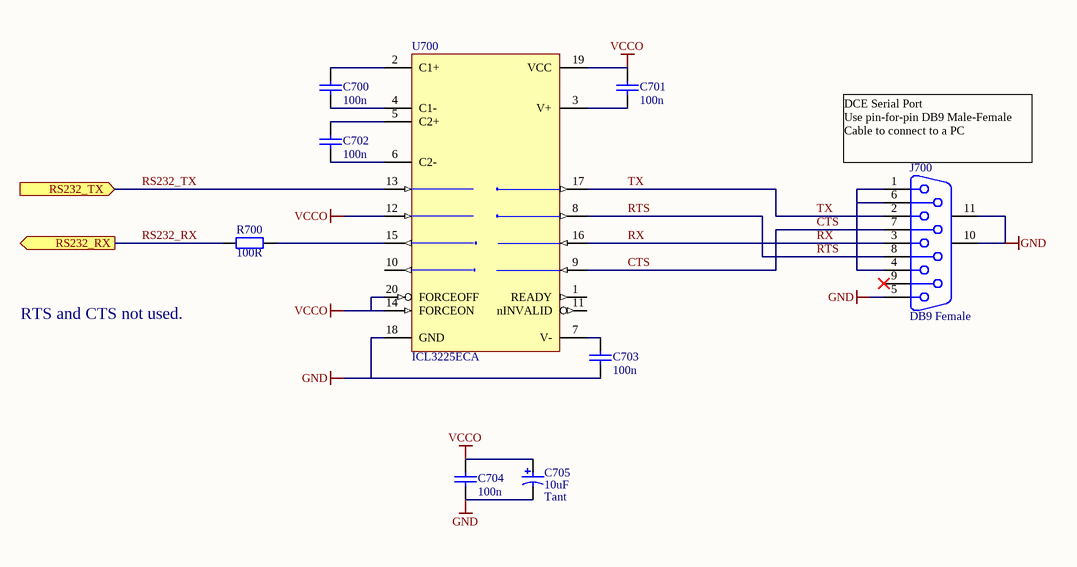
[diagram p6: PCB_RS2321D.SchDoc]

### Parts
C700  100n  [CC2012-0805]
C701  100n  [CC2012-0805]
C702  100n  [CC2012-0805]
C703  100n  [CC2012-0805]
C704  100n  [CC2012-0805]
C705  10uF  Capacitor Type: Tant  [MCCT-B]
J700  DB9 Female  [DSUB1.385-2H9]
R700  100R  [CC2012-0805]
U700  ICL3225ECA  [SSO-G20/P.65]

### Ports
RS232_RX (out), RS232_TX (in)

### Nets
GND: C703.2 C704.2 C705.2 J700.5 J700.10(MH1) J700.11(MH2) U700.18(GND)
VCCO: C701.1 C704.1 C705.1 U700.12(T2IN) U700.14(FORCEON) U700.19(VCC) U700.20(FORCEOFF)
CTS: J700.7 U700.9(R2IN)
RS232_RX: R700.2 ; port RS232_RX
RS232_TX: U700.13(T1IN) ; port RS232_TX
RTS: J700.8 U700.8(T2OUT)
RX: J700.3 U700.16(R1IN)
TX: J700.2 U700.17(T1OUT)
NetC700_1: C700.1 U700.2(C1+)
NetC700_2: C700.2 U700.4(C1-)
NetC701_2: C701.2 U700.3(V+)
NetC702_1: C702.1 U700.5(C2+)
NetC702_2: C702.2 U700.6(C2-)
NetC703_1: C703.1 U700.7(V-)
NetJ700_1: J700.1 J700.4 J700.6
NetR700_1: R700.1 U700.15(R1OUT)

Not connected (* = marked no-connect by the designer): J700 9*; U700 1(READY) 10(R2OUT) 11(nINVALID)

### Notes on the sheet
- (near J700) DCE Serial Port
  Use pin-for-pin DB9 Male-Female
  Cable to connect to a PC
- RTS and CTS not used.

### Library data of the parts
C700-C704 = CAP: Capacitor; Fitted: True
C705 = CAP_POLAR: Polar Capacitor; Fitted: True
J700 = D Connector 9: Receptacle Assembly, 9 Position, Right Angle; Manufacturer: Generic Components; Package Information: Latest Revision: O; Positions: 9; Fitted: True
R700 = Res2: as R600 on sheet PCB_Power1D
U700 = ICL3225ECA: 3.0V TO 5.5V, Low-Power, up to 1Mbps, True RS-232 Transceiver Using Four 0.1µF External Capacitor

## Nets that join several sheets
5V: PCB_Power1D (6 pins), PortIO (JP400_PortIOD.27 JP400_PortIOD.29 JP400_PortIOD.31 JP400_PortIOD.33), PortIO (JP400_PortIOC.27 JP400_PortIOC.29 JP400_PortIOC.31 JP400_PortIOC.33), PortIO (JP400_PortIOB.27 JP400_PortIOB.29 JP400_PortIOB.31 JP400_PortIOB.33), PortIO (JP400_PortIOA.27 JP400_PortIOA.29 JP400_PortIOA.31 JP400_PortIOA.33), FPGA Symbol1 (C232.1 U200.14)
GND: PCB_Power1D (28 pins), PCB_JTAG1D (18 pins), PortIO (35 pins), PortIO (35 pins), PortIO (35 pins), PortIO (35 pins), FPGA Symbol1 (38 pins), FPGA Sheet1 (27 pins), PCB_RS2321D (7 pins)
VCCINT: PCB_Power1D (C603.1 C606.1 R601.2 U601.2), FPGA Symbol1 (14 pins), FPGA Sheet1 (12 pins)
VCCO: PCB_Power1D (C601.1 C604.1 R600.2 U600.2), PCB_JTAG1D (14 pins), PortIO (JP400_PortIOD.28 JP400_PortIOD.30 JP400_PortIOD.32 JP400_PortIOD.34), PortIO (JP400_PortIOC.28 JP400_PortIOC.30 JP400_PortIOC.32 JP400_PortIOC.34), PortIO (JP400_PortIOB.28 JP400_PortIOB.30 JP400_PortIOB.32 JP400_PortIOB.34), PortIO (JP400_PortIOA.28 JP400_PortIOA.30 JP400_PortIOA.32 JP400_PortIOA.34), FPGA Symbol1 (26 pins), FPGA Sheet1 (16 pins), PCB_RS2321D (7 pins)
CCLK: PCB_JTAG1D (U501.3), FPGA Sheet1 (U1.155)
CFG_DIN: PCB_JTAG1D (U501.1), FPGA Sheet1 (U1.153)
CFG_INIT: PCB_JTAG1D (RA500.2 U501.8), FPGA Sheet1 (U1.107)
CLK_BRD: FPGA Symbol1 (U201.2), FPGA Sheet1 (U1.182)
DONE: PCB_JTAG1D (R500.2 U501.10), FPGA Sheet1 (U1.104)
INA0: PortIO (RA401_PortIOA.5 RA402_PortIOA.8), FPGA Sheet1 (U1.154)
INA1: PortIO (RA401_PortIOA.6 RA402_PortIOA.7), FPGA Sheet1 (U1.152)
INA2: PortIO (RA401_PortIOA.7 RA402_PortIOA.6), FPGA Sheet1 (U1.151)
INA3: PortIO (RA401_PortIOA.8 RA402_PortIOA.5), FPGA Sheet1 (U1.150)
INA4: PortIO (RA404_PortIOA.8 RA406_PortIOA.5), FPGA Sheet1 (U1.149)
INA5: PortIO (RA404_PortIOA.7 RA406_PortIOA.6), FPGA Sheet1 (U1.148)
INA6: PortIO (RA404_PortIOA.6 RA406_PortIOA.7), FPGA Sheet1 (U1.147)
INA7: PortIO (RA404_PortIOA.5 RA406_PortIOA.8), FPGA Sheet1 (U1.146)
INA8: PortIO (RA403_PortIOA.8 RA407_PortIOA.5), FPGA Sheet1 (U1.145)
INA9: PortIO (RA403_PortIOA.7 RA407_PortIOA.6), FPGA Sheet1 (U1.141)
INA10: PortIO (RA403_PortIOA.6 RA407_PortIOA.7), FPGA Sheet1 (U1.140)
INA11: PortIO (RA403_PortIOA.5 RA407_PortIOA.8), FPGA Sheet1 (U1.139)
INA12: PortIO (RA400_PortIOA.5 RA405_PortIOA.8), FPGA Sheet1 (U1.138)
INA13: PortIO (RA400_PortIOA.6 RA405_PortIOA.7), FPGA Sheet1 (U1.136)
INA14: PortIO (RA400_PortIOA.7 RA405_PortIOA.6), FPGA Sheet1 (U1.135)
INA15: PortIO (RA400_PortIOA.8 RA405_PortIOA.5), FPGA Sheet1 (U1.134)
INA16: PortIO (R401_PortIOA.2 R402_PortIOA.1), FPGA Sheet1 (U1.133)
INB0: PortIO (RA401_PortIOB.5 RA402_PortIOB.8), FPGA Sheet1 (U1.206)
INB1: PortIO (RA401_PortIOB.6 RA402_PortIOB.7), FPGA Sheet1 (U1.205)
INB2: PortIO (RA401_PortIOB.7 RA402_PortIOB.6), FPGA Sheet1 (U1.204)
INB3: PortIO (RA401_PortIOB.8 RA402_PortIOB.5), FPGA Sheet1 (U1.203)
INB4: PortIO (RA404_PortIOB.8 RA406_PortIOB.5), FPGA Sheet1 (U1.202)
INB5: PortIO (RA404_PortIOB.7 RA406_PortIOB.6), FPGA Sheet1 (U1.201)
INB6: PortIO (RA404_PortIOB.6 RA406_PortIOB.7), FPGA Sheet1 (U1.200)
INB7: PortIO (RA404_PortIOB.5 RA406_PortIOB.8), FPGA Sheet1 (U1.199)
INB8: PortIO (RA403_PortIOB.8 RA407_PortIOB.5), FPGA Sheet1 (U1.198)
INB9: PortIO (RA403_PortIOB.7 RA407_PortIOB.6), FPGA Sheet1 (U1.194)
INB10: PortIO (RA403_PortIOB.6 RA407_PortIOB.7), FPGA Sheet1 (U1.193)
INB11: PortIO (RA403_PortIOB.5 RA407_PortIOB.8), FPGA Sheet1 (U1.192)
INB12: PortIO (RA400_PortIOB.5 RA405_PortIOB.8), FPGA Sheet1 (U1.191)
INB13: PortIO (RA400_PortIOB.6 RA405_PortIOB.7), FPGA Sheet1 (U1.189)
INB14: PortIO (RA400_PortIOB.7 RA405_PortIOB.6), FPGA Sheet1 (U1.188)
INB15: PortIO (RA400_PortIOB.8 RA405_PortIOB.5), FPGA Sheet1 (U1.187)
INB16: PortIO (R401_PortIOB.2 R402_PortIOB.1), FPGA Sheet1 (U1.185)
INC0: PortIO (RA401_PortIOC.5 RA402_PortIOC.8), FPGA Sheet1 (U1.48)
INC1: PortIO (RA401_PortIOC.6 RA402_PortIOC.7), FPGA Sheet1 (U1.47)
INC2: PortIO (RA401_PortIOC.7 RA402_PortIOC.6), FPGA Sheet1 (U1.46)
INC3: PortIO (RA401_PortIOC.8 RA402_PortIOC.5), FPGA Sheet1 (U1.45)
INC4: PortIO (RA404_PortIOC.8 RA406_PortIOC.5), FPGA Sheet1 (U1.44)
INC5: PortIO (RA404_PortIOC.7 RA406_PortIOC.6), FPGA Sheet1 (U1.43)
INC6: PortIO (RA404_PortIOC.6 RA406_PortIOC.7), FPGA Sheet1 (U1.42)
INC7: PortIO (RA404_PortIOC.5 RA406_PortIOC.8), FPGA Sheet1 (U1.41)
INC8: PortIO (RA403_PortIOC.8 RA407_PortIOC.5), FPGA Sheet1 (U1.40)
INC9: PortIO (RA403_PortIOC.7 RA407_PortIOC.6), FPGA Sheet1 (U1.36)
INC10: PortIO (RA403_PortIOC.6 RA407_PortIOC.7), FPGA Sheet1 (U1.35)
INC11: PortIO (RA403_PortIOC.5 RA407_PortIOC.8), FPGA Sheet1 (U1.34)
INC12: PortIO (RA400_PortIOC.5 RA405_PortIOC.8), FPGA Sheet1 (U1.33)
INC13: PortIO (RA400_PortIOC.6 RA405_PortIOC.7), FPGA Sheet1 (U1.31)
INC14: PortIO (RA400_PortIOC.7 RA405_PortIOC.6), FPGA Sheet1 (U1.30)
INC15: PortIO (RA400_PortIOC.8 RA405_PortIOC.5), FPGA Sheet1 (U1.29)
INC16: PortIO (R401_PortIOC.2 R402_PortIOC.1), FPGA Sheet1 (U1.27)
IND0: PortIO (RA401_PortIOD.5 RA402_PortIOD.8), FPGA Sheet1 (U1.101)
IND1: PortIO (RA401_PortIOD.6 RA402_PortIOD.7), FPGA Sheet1 (U1.98)
IND2: PortIO (RA401_PortIOD.7 RA402_PortIOD.6), FPGA Sheet1 (U1.97)
IND3: PortIO (RA401_PortIOD.8 RA402_PortIOD.5), FPGA Sheet1 (U1.96)
IND4: PortIO (RA404_PortIOD.8 RA406_PortIOD.5), FPGA Sheet1 (U1.95)
IND5: PortIO (RA404_PortIOD.7 RA406_PortIOD.6), FPGA Sheet1 (U1.94)
IND6: PortIO (RA404_PortIOD.6 RA406_PortIOD.7), FPGA Sheet1 (U1.93)
IND7: PortIO (RA404_PortIOD.5 RA406_PortIOD.8), FPGA Sheet1 (U1.89)
IND8: PortIO (RA403_PortIOD.8 RA407_PortIOD.5), FPGA Sheet1 (U1.88)
IND9: PortIO (RA403_PortIOD.7 RA407_PortIOD.6), FPGA Sheet1 (U1.87)
IND10: PortIO (RA403_PortIOD.6 RA407_PortIOD.7), FPGA Sheet1 (U1.86)
IND11: PortIO (RA403_PortIOD.5 RA407_PortIOD.8), FPGA Sheet1 (U1.84)
IND12: PortIO (RA400_PortIOD.5 RA405_PortIOD.8), FPGA Sheet1 (U1.83)
IND13: PortIO (RA400_PortIOD.6 RA405_PortIOD.7), FPGA Sheet1 (U1.82)
IND14: PortIO (RA400_PortIOD.7 RA405_PortIOD.6), FPGA Sheet1 (U1.81)
IND15: PortIO (RA400_PortIOD.8 RA405_PortIOD.5), FPGA Sheet1 (U1.80)
IND16: PortIO (R401_PortIOD.2 R402_PortIOD.1), FPGA Sheet1 (U1.77)
JTAG_NEXUS_TCK: PCB_JTAG1D (RA503.2 RA505.3), FPGA Sheet1 (U1.160)
JTAG_NEXUS_TDI: PCB_JTAG1D (RA503.3 RA505.1), FPGA Sheet1 (U1.102)
JTAG_NEXUS_TDO: PCB_JTAG1D (RA505.2), FPGA Sheet1 (U1.100)
JTAG_NEXUS_TMS: PCB_JTAG1D (RA503.1 RA505.4), FPGA Sheet1 (U1.99)
OUTA0: PortIO (RA408_PortIOA.5), FPGA Sheet1 (U1.129)
OUTA1: PortIO (RA408_PortIOA.6), FPGA Sheet1 (U1.127)
OUTA2: PortIO (RA408_PortIOA.7), FPGA Sheet1 (U1.126)
OUTA3: PortIO (RA408_PortIOA.8), FPGA Sheet1 (U1.125)
OUTA4: PortIO (RA409_PortIOA.5), FPGA Sheet1 (U1.123)
OUTA5: PortIO (RA409_PortIOA.6), FPGA Sheet1 (U1.122)
OUTA6: PortIO (RA409_PortIOA.7), FPGA Sheet1 (U1.121)
OUTA7: PortIO (RA409_PortIOA.8), FPGA Sheet1 (U1.120)
OUTA8: PortIO (RA410_PortIOA.5), FPGA Sheet1 (U1.116)
OUTA9: PortIO (RA410_PortIOA.6), FPGA Sheet1 (U1.115)
OUTA10: PortIO (RA410_PortIOA.7), FPGA Sheet1 (U1.114)
OUTA11: PortIO (RA410_PortIOA.8), FPGA Sheet1 (U1.113)
OUTA12: PortIO (RA411_PortIOA.5), FPGA Sheet1 (U1.112)
OUTA13: PortIO (RA411_PortIOA.6), FPGA Sheet1 (U1.111)
OUTA14: PortIO (RA411_PortIOA.7), FPGA Sheet1 (U1.110)
OUTA15: PortIO (RA411_PortIOA.8), FPGA Sheet1 (U1.109)
OUTA16: PortIO (R403_PortIOA.1), FPGA Sheet1 (U1.108)
OUTB0: PortIO (RA408_PortIOB.5), FPGA Sheet1 (U1.181)
OUTB1: PortIO (RA408_PortIOB.6), FPGA Sheet1 (U1.180)
OUTB2: PortIO (RA408_PortIOB.7), FPGA Sheet1 (U1.179)
OUTB3: PortIO (RA408_PortIOB.8), FPGA Sheet1 (U1.178)
OUTB4: PortIO (RA409_PortIOB.5), FPGA Sheet1 (U1.176)
OUTB5: PortIO (RA409_PortIOB.6), FPGA Sheet1 (U1.175)
OUTB6: PortIO (RA409_PortIOB.7), FPGA Sheet1 (U1.174)
OUTB7: PortIO (RA409_PortIOB.8), FPGA Sheet1 (U1.173)
OUTB8: PortIO (RA410_PortIOB.5), FPGA Sheet1 (U1.169)
OUTB9: PortIO (RA410_PortIOB.6), FPGA Sheet1 (U1.168)
OUTB10: PortIO (RA410_PortIOB.7), FPGA Sheet1 (U1.167)
OUTB11: PortIO (RA410_PortIOB.8), FPGA Sheet1 (U1.166)
OUTB12: PortIO (RA411_PortIOB.5), FPGA Sheet1 (U1.165)
OUTB13: PortIO (RA411_PortIOB.6), FPGA Sheet1 (U1.164)
OUTB14: PortIO (RA411_PortIOB.7), FPGA Sheet1 (U1.163)
OUTB15: PortIO (RA411_PortIOB.8), FPGA Sheet1 (U1.162)
OUTB16: PortIO (R403_PortIOB.1), FPGA Sheet1 (U1.161)
OUTC0: PortIO (RA408_PortIOC.5), FPGA Sheet1 (U1.24)
OUTC1: PortIO (RA408_PortIOC.6), FPGA Sheet1 (U1.23)
OUTC2: PortIO (RA408_PortIOC.7), FPGA Sheet1 (U1.22)
OUTC3: PortIO (RA408_PortIOC.8), FPGA Sheet1 (U1.21)
OUTC4: PortIO (RA409_PortIOC.5), FPGA Sheet1 (U1.20)
OUTC5: PortIO (RA409_PortIOC.6), FPGA Sheet1 (U1.18)
OUTC6: PortIO (RA409_PortIOC.7), FPGA Sheet1 (U1.17)
OUTC7: PortIO (RA409_PortIOC.8), FPGA Sheet1 (U1.16)
OUTC8: PortIO (RA410_PortIOC.5), FPGA Sheet1 (U1.15)
OUTC9: PortIO (RA410_PortIOC.6), FPGA Sheet1 (U1.11)
OUTC10: PortIO (RA410_PortIOC.7), FPGA Sheet1 (U1.10)
OUTC11: PortIO (RA410_PortIOC.8), FPGA Sheet1 (U1.9)
OUTC12: PortIO (RA411_PortIOC.5), FPGA Sheet1 (U1.8)
OUTC13: PortIO (RA411_PortIOC.6), FPGA Sheet1 (U1.7)
OUTC14: PortIO (RA411_PortIOC.7), FPGA Sheet1 (U1.6)
OUTC15: PortIO (RA411_PortIOC.8), FPGA Sheet1 (U1.5)
OUTC16: PortIO (R403_PortIOC.1), FPGA Sheet1 (U1.4)
OUTD0: PortIO (RA408_PortIOD.5), FPGA Sheet1 (U1.74)
OUTD1: PortIO (RA408_PortIOD.6), FPGA Sheet1 (U1.73)
OUTD2: PortIO (RA408_PortIOD.7), FPGA Sheet1 (U1.71)
OUTD3: PortIO (RA408_PortIOD.8), FPGA Sheet1 (U1.70)
OUTD4: PortIO (RA409_PortIOD.5), FPGA Sheet1 (U1.69)
OUTD5: PortIO (RA409_PortIOD.6), FPGA Sheet1 (U1.68)
OUTD6: PortIO (RA409_PortIOD.7), FPGA Sheet1 (U1.64)
OUTD7: PortIO (RA409_PortIOD.8), FPGA Sheet1 (U1.63)
OUTD8: PortIO (RA410_PortIOD.5), FPGA Sheet1 (U1.62)
OUTD9: PortIO (RA410_PortIOD.6), FPGA Sheet1 (U1.61)
OUTD10: PortIO (RA410_PortIOD.7), FPGA Sheet1 (U1.60)
OUTD11: PortIO (RA410_PortIOD.8), FPGA Sheet1 (U1.59)
OUTD12: PortIO (RA411_PortIOD.5), FPGA Sheet1 (U1.58)
OUTD13: PortIO (RA411_PortIOD.6), FPGA Sheet1 (U1.57)
OUTD14: PortIO (RA411_PortIOD.7), FPGA Sheet1 (U1.56)
OUTD15: PortIO (RA411_PortIOD.8), FPGA Sheet1 (U1.55)
OUTD16: PortIO (R403_PortIOD.1), FPGA Sheet1 (U1.49)
PROGRAM: PCB_JTAG1D (RA500.1 U501.7), FPGA Sheet1 (U1.106)
RS232_RX: FPGA Sheet1 (U1.75), PCB_RS2321D (R700.2)
RS232_TX: FPGA Sheet1 (U1.3), PCB_RS2321D (U700.13)
TCK: PCB_JTAG1D (RA502.3 RA504.3 U500.13), FPGA Sheet1 (U1.207)
TDI: PCB_JTAG1D (U500.9), FPGA Sheet1 (U1.159)
TDO: PCB_JTAG1D (RA504.2), FPGA Sheet1 (U1.157)
TEST_BUTTON: FPGA Symbol1 (R200.1 SW200.1 SW200.2), FPGA Sheet1 (U1.132)
TMS: PCB_JTAG1D (RA502.2 RA504.4 U500.6), FPGA Sheet1 (U1.2)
